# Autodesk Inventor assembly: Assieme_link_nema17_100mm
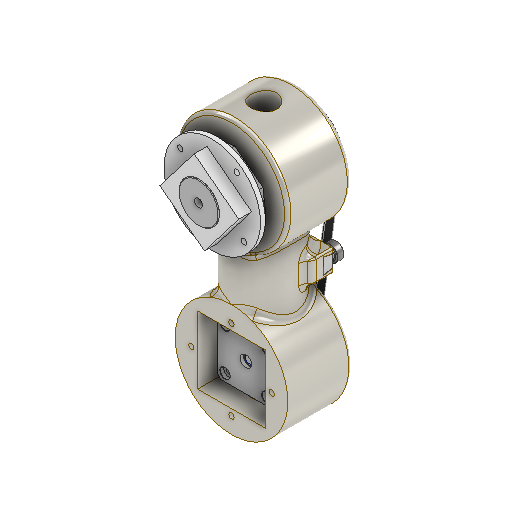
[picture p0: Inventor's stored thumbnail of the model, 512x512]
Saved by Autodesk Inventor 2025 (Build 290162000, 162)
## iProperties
Created: 2025-05
Part Number: Assieme_link_nema17_100mm
Document SubType Name: Assembly
Designer: 18907419
Author: 18907419
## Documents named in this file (10)
- C:\Users\R5800u\Desktop\robot v3\Assieme_link_nema17_100mm.iam
- C:\Users\R5800u\Desktop\robot v3\NEMA_14-13mm.iam
- C:\Users\R5800u\Desktop\robot v3\gt2-60.ipt
- C:\Users\R5800u\Desktop\robot v3\cinghia.ipt
- C:\Users\R5800u\Desktop\robot v3\blocco_tendi.ipt
- C:\Users\R5800u\Documents\Inventor\Content Center Files\R2025\it-IT\BS 290 SKF(30)\BS 290 SKF - SKF 623.ipt
- C:\Users\R5800u\Desktop\robot v3\6705-2RS.ipt
- C:\Users\R5800u\Documents\Inventor\Content Center Files\R2025\it-IT\AS 1420\AS 1420 - 1973 - M3 x 6.ipt
- C:\Users\R5800u\Desktop\robot v3\blocco_nema17.ipt
- C:\Users\R5800u\Desktop\robot v3\blocco_quadrato.ipt
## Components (10 placed, 9 different names)
1. blocco_nema17:1 — Coincidente:64, Allineato:11, Coincidente:65, Coincidente:66, Coincidente:67, Allineato:14, Rotazionale:25, Rotazionale:26, Coincidente:74, Rigido:1, Angolo:1, Coincidente:78
2. NEMA_14HM11-0404S:4 [sub-assembly] — Coincidente:66, Coincidente:67, Coincidente:73, Allineato:15
3. cinghia:1 — Coincidente:73, Coincidente:76, Allineato:16
4. blocco_tendi:1 — Allineato:14, Rigido:1, Rotazionale:27
5. 6705-2RS:3 — Rotazionale:25
6. 6705-2RS:4 — Rotazionale:26, Coincidente:75
7. gt2-60:1 — Coincidente:74, Coincidente:75, Allineato:15, Coincidente:76, Angolo:1, Allineato:16, Coincidente:77
8. BS 290 SKF 623:1 — Rotazionale:27
9. AS 1420 - Metrico M3 x 6:1
10. blocco_quadrato:1 — Coincidente:77, Coincidente:78
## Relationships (19: Mate 10, Flush 4, RevoluteJoint 3, WeldJoint 1, Angle 1)
- Coincidente:64 [Mate]: blocco_nema17:1
- Allineato:11 [Flush]: blocco_nema17:1
- Coincidente:65 [Mate]: blocco_nema17:1
- Coincidente:66 [Mate]: blocco_nema17:1 ↔ NEMA_14HM11-0404S:4
- Coincidente:67 [Mate]: blocco_nema17:1 ↔ NEMA_14HM11-0404S:4
- Allineato:14 [Flush]: blocco_nema17:1 ↔ blocco_tendi:1
- Rotazionale:25 [RevoluteJoint]: blocco_nema17:1 ↔ 6705-2RS:3
- Coincidente:73 [Mate]: NEMA_14HM11-0404S:4 ↔ cinghia:1
- Rotazionale:26 [RevoluteJoint]: blocco_nema17:1 ↔ 6705-2RS:4
- Coincidente:74 [Mate]: blocco_nema17:1 ↔ gt2-60:1
- Coincidente:75 [Mate]: 6705-2RS:4 ↔ gt2-60:1
- Allineato:15 [Flush]: NEMA_14HM11-0404S:4 ↔ gt2-60:1
- Coincidente:76 [Mate]: cinghia:1 ↔ gt2-60:1
- Rigido:1 [WeldJoint]: blocco_nema17:1 ↔ blocco_tendi:1
- Angolo:1 [Angle]: blocco_nema17:1 ↔ gt2-60:1
- Allineato:16 [Flush]: cinghia:1 ↔ gt2-60:1
- Rotazionale:27 [RevoluteJoint]: blocco_tendi:1 ↔ BS 290 SKF 623:1
- Coincidente:77 [Mate]: gt2-60:1 ↔ blocco_quadrato:1
- Coincidente:78 [Mate]: blocco_nema17:1 ↔ blocco_quadrato:1
